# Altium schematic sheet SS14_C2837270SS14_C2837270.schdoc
size 127 x 101 mm
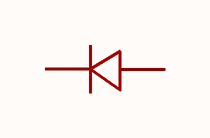
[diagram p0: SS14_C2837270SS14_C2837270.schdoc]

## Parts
D?  ss14_c2837270  [SMA_L4.3-W2.6-LS5.0-RD]  (value not drawn)

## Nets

Not connected (* = marked no-connect by the designer): D? 1(C) 2(A)

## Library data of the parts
D? = ss14_c2837270: 二极管配置:1个独立式;正向压降(Vf):550mV@1A;直流反向耐压(Vr):40V;整流电流:1A;; Manufacturer: JSMSEMI(杰盛微); ManufacturerPart: SS14; AddInBom: yes; ModelId: 8d2dd2e50a3a4b27821fa63d469a8f11; ModelTransform: 196.85,102.362,0,0,0,0,0,0,0; Diode Configuration: 1个独立式; Voltage - DC Reverse(Vr): 40V; Current - Rectified: 1A; Reverse Leakage Current (Ir): 500uA@40V; Operating Junction Temperature Range: -55℃~+125℃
